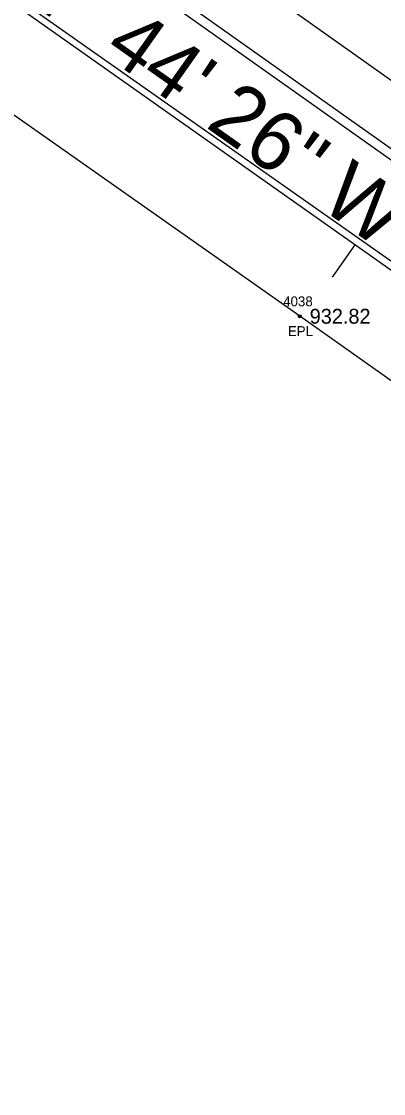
# Model space of a CAD drawing. Extents: x 1575382 to 1578175, y 1099175 to 1101955.
# Drawn here: x 1577218.2 to 1577254.7, y 1101291.9 to 1101400.1 of the extents above; entities that cross this region are included whole.
import ezdxf

# ---------------------------------------------------------------- set-up
doc = ezdxf.new("R2010")
doc.units = 0
for name, color, linetype in [('RD_EX_Conc', 7, 'Continuous'), ('RD_EX_Road', 7, 'Continuous'), ('RD_EX_Road_txCode', 7, 'Continuous'), ('RD_EX_TX_Road_ELEV', 7, 'Continuous'), ('RD_EX_UT', 7, 'Continuous'), ('RD_HC_Cl', 7, 'Continuous'), ('RD_HC_Data', 7, 'Continuous'), ('RD_HC_Data_Tic', 7, 'Continuous'), ('RD_SMD_Locator', 7, 'Continuous')]:
    doc.layers.add(name, color=color, linetype=linetype)

msp = doc.modelspace()

# ---------------------------------------------------------------- linework, layer by layer
at = {"layer": 'RD_EX_Conc'}
for points in [[(1577305.91, 1101358.4), (1577259.94, 1101390.92), (1577231.61, 1101411.04), (1577219.42, 1101419.77), (1577221.24, 1101412.22)], [(1577306.23, 1101358.15), (1577304.05, 1101352.9), (1577257.21, 1101385.98), (1577216.1, 1101415.11)]]:
    msp.add_lwpolyline(points, dxfattribs=at)
at = {"layer": 'RD_EX_Road'}
for points in [[(1577350.99, 1101394.65), (1577333.62, 1101354.38), (1577330.31, 1101348.32), (1577323.84, 1101345.4), (1577317.43, 1101344.5), (1577311.61, 1101346.41), (1577303.25, 1101352.4), (1577256.62, 1101385.27), (1577215.6, 1101414.32), (1577175.52, 1101442.94), (1577135.2, 1101471.71)], [(1577206.43, 1101064.72), (1577225.66, 1101106.5), (1577239.19, 1101137.5), (1577259.23, 1101183.34), (1577279.15, 1101229.33), (1577299.03, 1101275.07), (1577314.41, 1101310.73), (1577314.92, 1101317.44), (1577309.62, 1101326.25), (1577295.81, 1101333.97), (1577286.61, 1101341.78), (1577246.23, 1101370.35), (1577205.32, 1101399.1), (1577164.91, 1101427.55), (1577123.31, 1101456.71)]]:
    msp.add_lwpolyline(points, dxfattribs=at)
at = {"layer": 'RD_EX_UT'}
msp.add_lwpolyline([(1577014.29, 1101543.33), (1577198.95, 1101415.64), (1577337.02, 1101318.59)], dxfattribs=at)
at = {"layer": 'RD_HC_Cl'}
msp.add_line((1577333.44, 1101319.83), (1577129.25, 1101464.19), dxfattribs=at)
at = {"layer": 'RD_HC_Data_Tic'}
msp.add_line((1577251.79, 1101377.56), (1577249.48, 1101374.29), dxfattribs=at)
at = {"layer": 'RD_SMD_Locator'}
msp.add_circle((1577246.23, 1101370.35), 0.15, dxfattribs=at)

# ---------------------------------------------------------------- texts
at = {"layer": 'RD_EX_Road_txCode'}
for s, p in [('4038', (1577244.56, 1101371.35)), ('EPL', (1577245.03, 1101368.35))]:
    msp.add_text(s, height=1, dxfattribs=at).set_placement(p)
at = {"layer": 'RD_EX_TX_Road_ELEV'}
msp.add_text('932.82', height=1.5, dxfattribs=at).set_placement((1577247.23, 1101369.6))
at = {"layer": 'RD_HC_Data'}
msp.add_text('N 54%%d 44\' 26" W', height=6, rotation=324.7406, dxfattribs=at).set_placement((1577207.98, 1101409.75))

doc.saveas('drawing.dxf')
